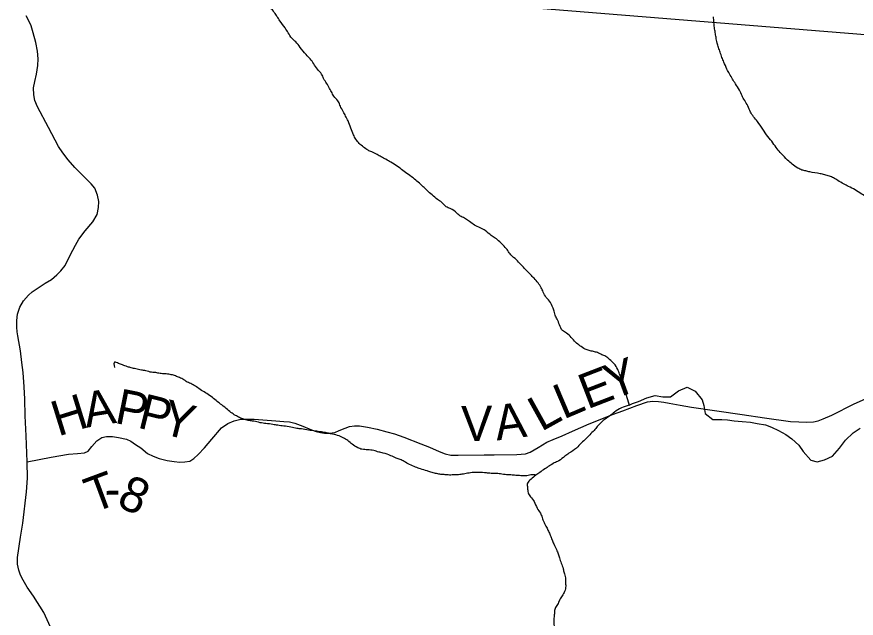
# Model space of a CAD drawing. Extents: x -13.7 to 34, y 0 to 32.3.
# Drawn here: x 27.091 to 28.447, y 18.005 to 18.977 of the extents above; entities that cross this region are included whole.
import ezdxf

# ---------------------------------------------------------------- set-up
doc = ezdxf.new("R2010")
doc.units = 0
for name, color, linetype in [('GM_X_Corporation', 7, 'Continuous'), ('GM_X_Minor_River', 7, 'Continuous'), ('GM_X_State_Route', 7, 'Continuous'), ('GM_X_Township_Road', 7, 'Continuous'), ('GM_X_Township_Road_Text', 7, 'Continuous')]:
    doc.layers.add(name, color=color, linetype=linetype)

msp = doc.modelspace()

# ---------------------------------------------------------------- linework, layer by layer
at = {"layer": 'GM_X_Corporation'}
msp.add_lwpolyline([(28.0076, 20.0028), (29.0337, 19.933), (28.9612, 18.9069), (27.9343, 18.9903)], close=True, dxfattribs=at)
at = {"layer": 'GM_X_Minor_River'}
for points in [[(28.0645, 18.3997), (28.0711, 18.3789), (28.0774, 18.3586), (28.0801, 18.3497)], [(28.0801, 18.3497), (28.0853, 18.3524), (28.0951, 18.3554), (28.1084, 18.3615), (28.122, 18.3653), (28.1342, 18.3631), (28.147, 18.3631), (28.1599, 18.3726), (28.1735, 18.3783), (28.1864, 18.3722), (28.1982, 18.3582), (28.2009, 18.3488), (28.2028, 18.3359), (28.2153, 18.3264), (28.2297, 18.3261), (28.2391, 18.3257), (28.2498, 18.3242), (28.2626, 18.3231), (28.2759, 18.322), (28.2869, 18.3201), (28.3002, 18.3179), (28.31, 18.3141), (28.3214, 18.3084), (28.3328, 18.302), (28.3426, 18.2952), (28.354, 18.2846), (28.3608, 18.2744), (28.3733, 18.2607), (28.3836, 18.2581), (28.3957, 18.2612), (28.4086, 18.2672), (28.4199, 18.2801), (28.4294, 18.2927), (28.4415, 18.3048), (28.4532, 18.3124)]]:
    msp.add_lwpolyline(points, dxfattribs=at)
for points in [[(28.0645, 18.3997), (28.0617, 18.407), (28.0555, 18.4167), (28.0485, 18.4234), (28.0422, 18.4281), (28.0359, 18.431), (28.0288, 18.4343), (28.0224, 18.436), (28.0156, 18.4377), (28.0088, 18.4399), (28.0007, 18.4455), (27.9936, 18.451), (27.9867, 18.4588), (27.979, 18.4659), (27.9726, 18.4699), (27.9676, 18.4792), (27.9638, 18.4885), (27.9606, 18.495), (27.9582, 18.5031), (27.9529, 18.5151), (27.9463, 18.5236), (27.9413, 18.5322), (27.9381, 18.5391), (27.933, 18.5469), (27.9268, 18.5543), (27.9206, 18.5606), (27.9111, 18.5704), (27.9044, 18.5771), (27.8982, 18.5841), (27.889, 18.5924), (27.8843, 18.599), (27.8784, 18.606), (27.8711, 18.6131), (27.8637, 18.6194), (27.8574, 18.6235), (27.8478, 18.6314), (27.8306, 18.6403), (27.8224, 18.6459), (27.8161, 18.6503), (27.8087, 18.6543), (27.802, 18.6595), (27.7913, 18.6671), (27.7849, 18.6699), (27.7775, 18.677), (27.7705, 18.6818), (27.762, 18.6889), (27.7539, 18.696), (27.7476, 18.7023), (27.7414, 18.7078), (27.7336, 18.7146), (27.7236, 18.7221), (27.7147, 18.7285), (27.7055, 18.7353), (27.6954, 18.7417), (27.6872, 18.7465), (27.6798, 18.7505), (27.6734, 18.7542), (27.6648, 18.7586), (27.6585, 18.7611), (27.6511, 18.7663), (27.6444, 18.7722), (27.6389, 18.7789), (27.635, 18.7862), (27.6308, 18.797), (27.6263, 18.8085), (27.6223, 18.8163), (27.6184, 18.8236), (27.6138, 18.8325), (27.611, 18.8391), (27.6047, 18.8465), (27.6004, 18.8538), (27.5965, 18.8608), (27.5915, 18.8693), (27.5868, 18.8771), (27.5836, 18.884), (27.5767, 18.8922), (27.5709, 18.9008), (27.565, 18.9086), (27.5585, 18.9156), (27.549, 18.9273), (27.5417, 18.936), (27.5354, 18.9419), (27.5296, 18.9508), (27.5246, 18.9586), (27.5162, 18.9702), (27.5115, 18.9772), (27.5072, 18.9838), (27.5006, 18.9916), (27.494, 18.9976), (27.4862, 19.0039), (27.4792, 19.0098), (27.4699, 19.0151), (27.4635, 19.0179), (27.4533, 19.0183), (27.4468, 19.0181), (27.4381, 19.0176), (27.4309, 19.0175)], [(28.7426, 18.3371), (28.7453, 18.3604), (28.7453, 18.3703), (28.7447, 18.3767), (28.7446, 18.3836), (28.7449, 18.3931), (28.7439, 18.4091), (28.7419, 18.419), (28.739, 18.4328), (28.7363, 18.4431), (28.734, 18.4535), (28.7302, 18.4665), (28.7271, 18.475), (28.7214, 18.4881), (28.7175, 18.4958), (28.7139, 18.5024), (28.7096, 18.5094), (28.7049, 18.5167), (28.6999, 18.5245), (28.6941, 18.5327), (28.6894, 18.5393), (28.6831, 18.5467), (28.6744, 18.5573), (28.6678, 18.5651), (28.6613, 18.5752), (28.6566, 18.5818), (28.65, 18.5896), (28.6419, 18.5978), (28.6335, 18.6065), (28.6265, 18.6124), (28.6161, 18.6196), (28.6086, 18.624), (28.5982, 18.6304), (28.5907, 18.6337), (28.5826, 18.6393), (28.5762, 18.643), (28.5688, 18.6474), (28.5617, 18.651), (28.5545, 18.6517), (28.5466, 18.6523), (28.5382, 18.6522), (28.5318, 18.6528), (28.5238, 18.6527), (28.5173, 18.6521), (28.5102, 18.6531), (28.5001, 18.6592), (28.4934, 18.6643), (28.486, 18.6691), (28.4797, 18.6735), (28.4731, 18.679), (28.4638, 18.6851), (28.4548, 18.691), (28.4448, 18.6971), (28.4344, 18.7027), (28.4261, 18.7068), (28.4172, 18.7121), (28.4098, 18.7165), (28.4034, 18.7193), (28.3959, 18.7215), (28.3883, 18.7233), (28.3717, 18.7261), (28.3653, 18.7278), (28.3589, 18.7292), (28.3522, 18.7324), (28.3433, 18.7388), (28.3359, 18.7451), (28.3256, 18.7557), (28.3191, 18.7632), (28.3122, 18.7729), (28.3042, 18.7834), (28.2958, 18.7951), (28.2871, 18.8075), (28.2809, 18.8153), (28.2762, 18.8227), (28.2716, 18.8328), (28.2666, 18.8417), (28.2623, 18.849), (28.2581, 18.8583), (28.2519, 18.8684), (28.2469, 18.8761), (28.2422, 18.8846), (28.2379, 18.892), (28.233, 18.9036), (28.2298, 18.9109), (28.2271, 18.9193), (28.2243, 18.927), (28.2222, 18.9343), (28.2203, 18.9435), (28.219, 18.9511), (28.2178, 18.9595), (28.2169, 18.9675), (28.2164, 18.9767)], [(27.9297, 18.2365), (27.9236, 18.2371), (27.9151, 18.2355), (27.9053, 18.2355), (27.8969, 18.2361), (27.889, 18.2368), (27.8822, 18.237), (27.8723, 18.2385), (27.864, 18.2391), (27.8572, 18.2393), (27.8496, 18.24), (27.8367, 18.2408), (27.8288, 18.2407), (27.8192, 18.2395), (27.8101, 18.2379), (27.8028, 18.237), (27.7964, 18.2368), (27.7876, 18.2367), (27.7812, 18.2373), (27.7744, 18.2379), (27.7676, 18.2393), (27.7601, 18.2414), (27.7537, 18.2432), (27.7432, 18.2465), (27.7353, 18.2495), (27.7256, 18.2536), (27.717, 18.2584), (27.7103, 18.2617), (27.7039, 18.2638), (27.6953, 18.2679), (27.6829, 18.2721), (27.6757, 18.2738), (27.6678, 18.276), (27.658, 18.2775), (27.6486, 18.2782), (27.6418, 18.2807), (27.6329, 18.2863), (27.6259, 18.2922), (27.6184, 18.2966), (27.6094, 18.3007), (27.5981, 18.3034), (27.5917, 18.3047), (27.5831, 18.3062), (27.5732, 18.3076), (27.5623, 18.3091), (27.5509, 18.311), (27.5438, 18.312), (27.534, 18.3139), (27.5223, 18.3158), (27.5128, 18.3169), (27.5049, 18.3183), (27.4935, 18.3198), (27.4845, 18.3212), (27.4739, 18.3235), (27.4671, 18.3245), (27.4596, 18.3262), (27.4528, 18.3287), (27.4461, 18.332), (27.439, 18.3364), (27.4316, 18.3423), (27.4224, 18.3499), (27.415, 18.3554), (27.4072, 18.3618), (27.398, 18.3682), (27.3894, 18.3734), (27.3816, 18.379), (27.3742, 18.3834), (27.3667, 18.3867), (27.3593, 18.3915), (27.3525, 18.3947), (27.3462, 18.3972), (27.339, 18.399), (27.3303, 18.4), (27.3227, 18.4007), (27.3159, 18.402), (27.3091, 18.4026), (27.2997, 18.4048), (27.2926, 18.4062), (27.2835, 18.408), (27.2763, 18.4098), (27.27, 18.4115), (27.2621, 18.4145), (27.2557, 18.4169), (27.2493, 18.4191), (27.249, 18.4103)], [(28.0801, 18.3497), (28.0563, 18.3384), (28.0485, 18.3318), (28.0415, 18.3271), (28.0349, 18.3216), (28.0286, 18.315), (28.0235, 18.3087), (28.0164, 18.3017), (28.0105, 18.2954), (28.0031, 18.2885), (27.9948, 18.28), (27.9828, 18.2717), (27.9762, 18.2669), (27.9664, 18.2597), (27.9591, 18.2561), (27.9514, 18.2514), (27.944, 18.2467), (27.9358, 18.2409), (27.9292, 18.2362), (27.9218, 18.23), (27.9159, 18.2233), (27.916, 18.2161), (27.9169, 18.2081), (27.9209, 18.2015), (27.9267, 18.1937), (27.9316, 18.1829), (27.9367, 18.1752), (27.9395, 18.1682), (27.9426, 18.1601), (27.9466, 18.1524), (27.9498, 18.1458), (27.9526, 18.1393), (27.9557, 18.132), (27.9582, 18.1254), (27.9628, 18.1162), (27.9656, 18.1092), (27.9677, 18.1027), (27.9701, 18.0943)], [(27.9701, 18.0943), (27.9736, 18.0854), (27.9749, 18.0789), (27.9773, 18.0708), (27.9774, 18.0636), (27.9776, 18.0571), (27.9758, 18.0485), (27.9721, 18.0418), (27.9677, 18.0347), (27.9644, 18.0276), (27.9604, 18.0212), (27.9594, 18.0141), (27.9588, 18.0076), (27.9582, 17.9989), (27.9591, 17.9913), (27.9606, 17.9813), (27.9627, 17.9741), (27.9635, 17.966), (27.964, 17.958), (27.9649, 17.9512), (27.9666, 17.9443), (27.969, 17.9374), (27.9714, 17.9289), (27.9726, 17.9186), (27.9739, 17.911), (27.9744, 17.9037), (27.9772, 17.8964), (27.9822, 17.8887), (27.9843, 17.8821), (27.9876, 17.8684), (27.9897, 17.8603), (27.9912, 17.8508), (27.9932, 17.8423), (27.993, 17.8359), (27.9913, 17.8295), (27.9907, 17.8227), (27.9901, 17.8151), (27.9896, 17.7999), (27.9912, 17.7934), (27.9929, 17.7861), (27.9945, 17.7785), (27.9958, 17.7719), (27.9975, 17.7635), (27.9995, 17.7559), (28, 17.7486), (27.9986, 17.7415), (27.9957, 17.7336), (27.9894, 17.7258), (27.9824, 17.7203), (27.9758, 17.7183), (27.9674, 17.717), (27.9544, 17.7137), (27.9373, 17.7123), (27.9285, 17.7115), (27.9221, 17.7109), (27.9049, 17.7081), (27.8984, 17.7068), (27.8915, 17.7051), (27.8831, 17.7027), (27.8759, 17.7026), (27.8664, 17.7025), (27.8588, 17.702), (27.8504, 17.7019), (27.8261, 17.7027), (27.8182, 17.7041), (27.8103, 17.7059), (27.8027, 17.7065), (27.7853, 17.7079), (27.7789, 17.7085), (27.7717, 17.7091), (27.7634, 17.7101), (27.7547, 17.7112), (27.7445, 17.7123), (27.7346, 17.713), (27.7282, 17.7132), (27.7217, 17.7138), (27.7123, 17.7141), (27.7028, 17.7152), (27.6922, 17.7159), (27.6823, 17.7155), (27.6755, 17.7149), (27.6682, 17.7133), (27.6616, 17.7105), (27.6523, 17.7024), (27.6441, 17.697), (27.6367, 17.6904), (27.6286, 17.6861), (27.6193, 17.6822), (27.6113, 17.6806), (27.6006, 17.6794), (27.5931, 17.68), (27.5852, 17.6818), (27.578, 17.6832), (27.5693, 17.6843), (27.5593, 17.6911), (27.5527, 17.6981), (27.5456, 17.7025)]]:
    msp.add_spline(points, degree=3, dxfattribs=at)
at = {"layer": 'GM_X_State_Route'}
msp.add_lwpolyline([(27.146, 17.9912), (27.135, 18.0144), (27.1183, 18.041), (27.1081, 18.0556), (27.1015, 18.0669), (27.0976, 18.0749), (27.0945, 18.0829), (27.0927, 18.0925), (27.0923, 18.1034), (27.0976, 18.1363), (27.1011, 18.1588), (27.1073, 18.2097), (27.1087, 18.2317), (27.1081, 18.2581), (27.1063, 18.2997), (27.1047, 18.3323), (27.1042, 18.3592), (27.1032, 18.3788), (27.1018, 18.4023), (27.0996, 18.4182), (27.0975, 18.4373), (27.093, 18.4612), (27.092, 18.4681), (27.0916, 18.4755), (27.0914, 18.4861), (27.0928, 18.4963), (27.0961, 18.5077), (27.102, 18.5179), (27.1104, 18.5269), (27.1163, 18.5324), (27.1373, 18.5463), (27.1475, 18.5524), (27.1563, 18.5597), (27.1626, 18.5665), (27.1693, 18.575), (27.1777, 18.5915), (27.186, 18.6081), (27.1917, 18.6176), (27.2019, 18.6309), (27.214, 18.6455), (27.2211, 18.6576), (27.2234, 18.6686), (27.2236, 18.6786), (27.2219, 18.6884), (27.2174, 18.6998), (27.2117, 18.707), (27.1995, 18.719), (27.1852, 18.7331), (27.1742, 18.7455), (27.1658, 18.7568), (27.1587, 18.7672), (27.1424, 18.7977), (27.1251, 18.831), (27.1208, 18.8416), (27.1191, 18.8504), (27.1185, 18.8618), (27.1204, 18.8724), (27.123, 18.884), (27.1255, 18.8979), (27.1261, 18.9085), (27.1248, 18.9211), (27.1222, 18.935), (27.1181, 18.9509), (27.1146, 18.9623), (27.1104, 18.9711), (27.1067, 18.9784)], dxfattribs=at)
at = {"layer": 'GM_X_Township_Road'}
msp.add_lwpolyline([(27.1081, 18.2581), (27.1469, 18.2654), (27.1748, 18.2703), (27.1895, 18.2713), (27.2009, 18.2726), (27.2064, 18.2754), (27.2128, 18.2828), (27.2205, 18.2919), (27.2287, 18.297), (27.2362, 18.2989), (27.2458, 18.2987), (27.2558, 18.297), (27.2684, 18.2944), (27.2754, 18.2913), (27.2833, 18.2862), (27.2917, 18.2803), (27.3023, 18.2713), (27.3115, 18.2672), (27.3215, 18.2636), (27.3343, 18.2603), (27.3457, 18.2587), (27.3545, 18.2575), (27.3629, 18.2577), (27.3706, 18.2589), (27.3775, 18.2634), (27.3845, 18.2699), (27.3945, 18.2803), (27.4061, 18.2946), (27.422, 18.3131), (27.432, 18.3197), (27.4422, 18.3241), (27.4532, 18.3266), (27.4638, 18.3266), (27.4746, 18.3266), (27.4885, 18.3256), (27.5097, 18.3244), (27.5228, 18.3229), (27.5315, 18.3225), (27.5403, 18.3205), (27.5534, 18.3158), (27.5672, 18.3095), (27.575, 18.3068), (27.5819, 18.3052), (27.588, 18.3044), (27.5958, 18.3042), (27.6048, 18.3052), (27.6119, 18.3084), (27.6217, 18.3121), (27.6288, 18.3148), (27.6366, 18.316), (27.6447, 18.316), (27.6574, 18.3138), (27.6735, 18.3109), (27.6886, 18.3066), (27.7012, 18.3029), (27.7165, 18.2978), (27.7439, 18.2872), (27.7579, 18.2819), (27.7736, 18.2746), (27.783, 18.2707), (27.792, 18.2689), (27.8042, 18.2685), (27.8458, 18.2691), (27.8622, 18.2691), (27.8985, 18.2697), (27.9127, 18.2709), (27.9205, 18.2738), (27.9333, 18.2813), (27.947, 18.2897), (27.9574, 18.294), (27.9721, 18.3001), (27.9884, 18.3076), (28.0153, 18.3195), (28.0384, 18.3284), (28.0531, 18.3343), (28.0698, 18.3401), (28.0926, 18.349), (28.1096, 18.3549), (28.1185, 18.356), (28.1275, 18.3556), (28.1363, 18.3541), (28.1448, 18.3527), (28.1626, 18.3494), (28.1809, 18.346), (28.2623, 18.3344), (28.2984, 18.329), (28.3406, 18.3233), (28.3541, 18.3223), (28.3667, 18.3219), (28.3778, 18.3223), (28.3851, 18.3239), (28.3935, 18.3272), (28.4073, 18.3335), (28.4434, 18.3517), (28.4716, 18.3641)], dxfattribs=at)

# ---------------------------------------------------------------- texts
at = {"layer": 'GM_X_Township_Road_Text'}
for s, rotation, p in [('Y', 20.0917, (28.0519, 18.3576)), ('E', 21.0907, (28.0125, 18.3424)), ('L', 23.0286, (27.9739, 18.326)), ('H', 17.2645, (27.158, 18.2987)), ('A', 9.1383, (27.2037, 18.313)), ('P', 348.4958, (27.2477, 18.3211)), ('P', 346.0456, (27.2846, 18.3136)), ('Y', 345.8688, (27.3218, 18.3043)), ('A', 7.3459, (27.8664, 18.2923)), ('L', 29.0605, (27.9381, 18.306)), ('V', 0.5282, (27.809, 18.2914)), ('T', 20.3624, (27.2145, 18.175)), ('8', 335.8293, (27.2505, 18.1874)), ('-', 0.6334, (27.2335, 18.1859))]:
    msp.add_text(s, height=0.0568, rotation=rotation, dxfattribs=at).set_placement(p)

doc.saveas('drawing.dxf')
